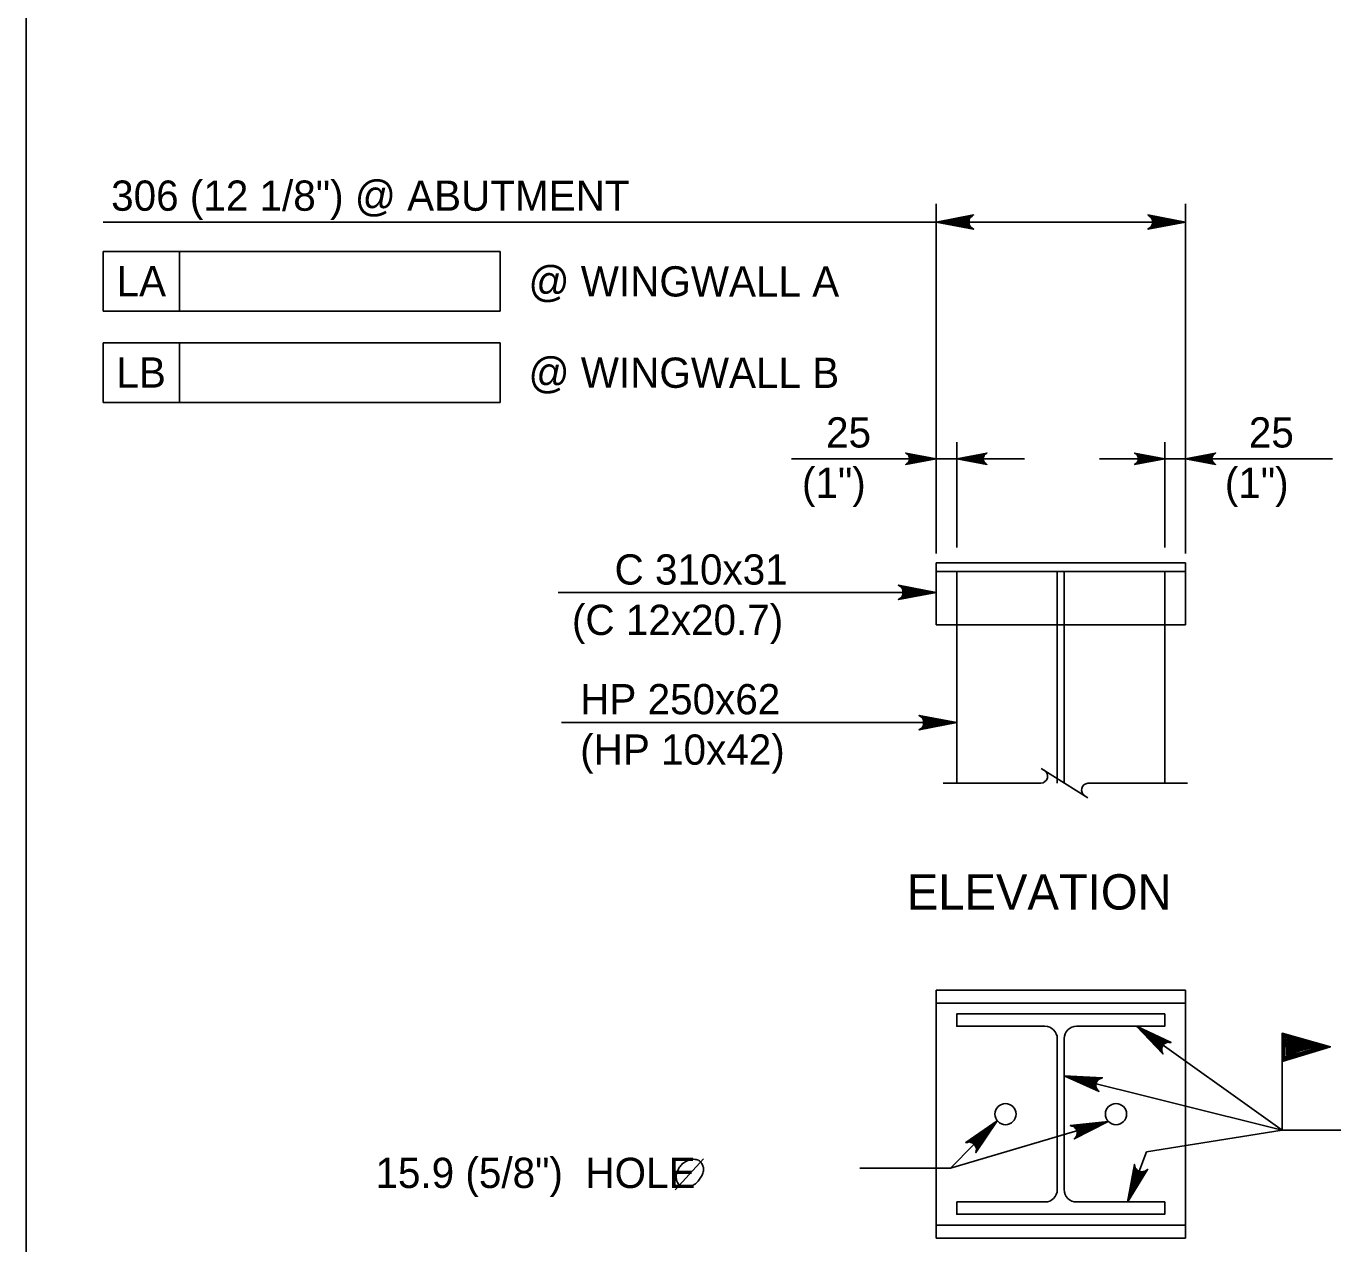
# Model space of a CAD drawing. Extents: x 635440 to 640306, y 296653 to 298484.
# Drawn here: x 639316.5 to 639446.1, y 296943.8 to 297064.6 of the extents above; entities that cross this region are included whole.
import ezdxf

# ---------------------------------------------------------------- set-up
doc = ezdxf.new("R2010")
doc.units = 0
for name, color, linetype in [('1', 7, 'Continuous'), ('2', 7, 'Continuous'), ('3', 7, 'Continuous'), ('4', 7, 'Continuous'), ('5', 7, 'Continuous')]:
    doc.layers.add(name, color=color, linetype=linetype)

# ---------------------------------------------------------------- blocks, each defined once
blk = doc.blocks.new('HPILE')
at = {"layer": '3'}
for p, q in [((-0.122, -2.665), (-0.122, 2.665)), ((0.122, 2.665), (0.122, -2.665)), ((-3.673, -3.102), (-0.56, -3.102))]:
    blk.add_line(p, q, dxfattribs=at)
for points in [[(-0.56, 3.102), (-3.673, 3.102), (-3.673, 3.537), (3.673, 3.537), (3.673, 3.102), (0.56, 3.102)], [(0.56, -3.102), (3.673, -3.102), (3.673, -3.536), (-3.673, -3.536), (-3.673, -3.102)]]:
    blk.add_lwpolyline(points, dxfattribs=at)
for centre, start, end in [((-0.56, 2.665), 0, 90), ((0.56, 2.665), 90, 180), ((-0.56, -2.665), 270, 0), ((0.56, -2.665), 180, 270)]:
    blk.add_arc(centre, 0.438, start, end, dxfattribs=at)
blk = doc.blocks.new('LT')
at = {"layer": '1'}
blk.add_lwpolyline([(0, 0), (-11.18, -2.1), (-10.75, -1.8), (-10.32, -1.5), (-10.1, -1.12), (-9.88, -0.75), (-9.81, -0.38), (-9.75, 0), (-9.81, 0.38), (-9.88, 0.75), (-10.1, 1.12), (-10.32, 1.5), (-10.75, 1.8), (-11.18, 2.1), (0, 0), (-10.75, 1.8), (-10.32, 1.5), (0, 0), (-10.1, 1.12), (-9.88, 0.75), (0, 0), (-9.81, 0.38), (-9.75, 0), (0, 0), (-9.81, -0.38), (-9.88, -0.75), (0, 0), (-10.1, -1.12), (-10.32, -1.5), (0, 0), (-10.75, -1.8)], dxfattribs=at)

msp = doc.modelspace()

# ---------------------------------------------------------------- linework, layer by layer
at = {"layer": '2'}
msp.add_line((639316.46, 296668.46), (639316.46, 297232.46), dxfattribs=at)
at = {"layer": '3'}
for p, q in [((639406.72, 297011.39), (639406.72, 297005.24)), ((639406.72, 297011.39), (639431.46, 297011.39)), ((639431.46, 297005.24), (639431.46, 297011.39)), ((639406.72, 297010.53), (639431.46, 297010.53)), ((639408.77, 297010.53), (639408.77, 297005.24)), ((639418.74, 297010.53), (639418.74, 296989.52)), ((639419.43, 297010.53), (639419.43, 296989.52)), ((639429.41, 297010.53), (639429.41, 297005.24)), ((639406.72, 297005.24), (639431.46, 297005.24)), ((639408.77, 297005.24), (639408.77, 296989.52)), ((639429.41, 296989.52), (639429.41, 297005.24)), ((639417.16, 296990.98), (639421.78, 296988.07)), ((639407.43, 296989.52), (639417.11, 296989.52)), ((639421.77, 296989.52), (639431.66, 296989.52)), ((639406.72, 296968.98), (639431.46, 296968.98)), ((639406.72, 296968.98), (639406.72, 296944.38)), ((639431.46, 296944.38), (639431.46, 296968.98)), ((639406.72, 296967.7), (639431.46, 296967.7)), ((639441.04, 296955.1), (639419.43, 296960.49)), ((639441.04, 296955.1), (639427.6, 296952.95)), ((639441.04, 296955.1), (639470.68, 296955.1)), ((639427.6, 296952.95), (639425.72, 296947.96)), ((639406.72, 296945.66), (639431.46, 296945.66)), ((639406.72, 296944.38), (639431.46, 296944.38))]:
    msp.add_line(p, q, dxfattribs=at)
for points in [[(639426.59, 296965.4), (639441.04, 296955.1)], [(639441.04, 296955.1), (639441.04, 296964.7), (639445.85, 296963.36), (639441.04, 296961.89), (639441.13, 296964.54), (639445.47, 296963.36), (639441.16, 296962.08), (639441.16, 296964.42), (639445.21, 296963.38), (639441.24, 296962.2), (639441.22, 296964.28), (639444.88, 296963.36), (639441.3, 296962.33), (639441.29, 296964.11), (639444.46, 296963.38), (639441.56, 296962.64), (639441.38, 296963.99), (639444.18, 296963.41), (639441.5, 296962.5), (639441.47, 296963.81), (639443.91, 296963.41), (639441.61, 296962.7), (639441.55, 296963.69), (639443.6, 296963.41), (639441.69, 296962.79), (639441.61, 296963.63), (639443.33, 296963.41), (639441.72, 296962.88), (639441.72, 296963.5), (639443.07, 296963.4), (639441.8, 296963.01), (639441.8, 296963.43), (639442.7, 296963.35), (639441.84, 296963.09), (639441.87, 296963.3), (639442.42, 296963.32), (639441.86, 296963.15), (639441.91, 296963.26), (639445.69, 296963.36), (639441.12, 296962), (639441.1, 296964.62)]]:
    msp.add_lwpolyline(points, dxfattribs=at)
for centre in [(639413.61, 296956.68), (639424.57, 296956.68)]:
    msp.add_circle(centre, 1.05, dxfattribs=at)
for centre, start, end in [((639417.11, 296990.21), 270, 60), ((639421.84, 296988.84), 95.3286, 237.8672)]:
    msp.add_arc(centre, 0.682, start, end, dxfattribs=at)
at = {"layer": '4'}
for p, q in [((639406.72, 297047.01), (639406.72, 297012.32)), ((639431.46, 297047.01), (639431.46, 297012.32)), ((639406.72, 297045.19), (639324.1, 297045.19)), ((639431.46, 297045.19), (639406.72, 297045.19)), ((639324.1, 297042.27), (639363.47, 297042.27)), ((639324.1, 297042.27), (639324.1, 297036.36)), ((639331.66, 297042.27), (639331.66, 297036.36)), ((639363.47, 297042.27), (639363.47, 297036.36)), ((639324.1, 297036.36), (639363.47, 297036.36)), ((639324.1, 297033.21), (639363.47, 297033.21)), ((639324.1, 297033.21), (639324.1, 297027.3)), ((639331.66, 297033.21), (639331.66, 297027.3)), ((639363.47, 297033.21), (639363.47, 297027.3)), ((639324.1, 297027.3), (639363.47, 297027.3)), ((639408.77, 297023.36), (639408.77, 297012.91)), ((639429.41, 297023.36), (639429.41, 297012.91)), ((639415.5, 297021.71), (639392.38, 297021.71)), ((639446.06, 297021.71), (639422.94, 297021.71))]:
    msp.add_line(p, q, dxfattribs=at)
for points in [[(639406.72, 297045.19), (639410.45, 297045.89), (639410.3, 297045.79), (639410.16, 297045.69), (639410.08, 297045.57), (639410.01, 297045.44), (639409.99, 297045.32), (639409.97, 297045.19), (639409.99, 297045.07), (639410.01, 297044.94), (639410.08, 297044.82), (639410.16, 297044.69), (639410.3, 297044.59), (639410.45, 297044.49), (639406.72, 297045.19), (639410.3, 297044.59), (639410.16, 297044.69), (639406.72, 297045.19), (639410.08, 297044.82), (639410.01, 297044.94), (639406.72, 297045.19), (639409.99, 297045.07), (639409.97, 297045.19), (639406.72, 297045.19), (639409.99, 297045.32), (639410.01, 297045.44), (639406.72, 297045.19), (639410.08, 297045.57), (639410.16, 297045.69), (639406.72, 297045.19), (639410.3, 297045.79)], [(639431.46, 297045.19), (639427.73, 297044.49), (639427.87, 297044.59), (639428.02, 297044.69), (639428.09, 297044.82), (639428.17, 297044.94), (639428.19, 297045.07), (639428.21, 297045.19), (639428.19, 297045.32), (639428.17, 297045.44), (639428.09, 297045.57), (639428.02, 297045.69), (639427.87, 297045.79), (639427.73, 297045.89), (639431.46, 297045.19), (639427.87, 297045.79), (639428.02, 297045.69), (639431.46, 297045.19), (639428.09, 297045.57), (639428.17, 297045.44), (639431.46, 297045.19), (639428.19, 297045.32), (639428.21, 297045.19), (639431.46, 297045.19), (639428.19, 297045.07), (639428.17, 297044.94), (639431.46, 297045.19), (639428.09, 297044.82), (639428.02, 297044.69), (639431.46, 297045.19), (639427.87, 297044.59)], [(639406.72, 297008.45), (639369.24, 297008.45)], [(639406.72, 297008.45), (639402.99, 297007.75), (639403.13, 297007.85), (639403.28, 297007.95), (639403.35, 297008.07), (639403.42, 297008.2), (639403.44, 297008.32), (639403.47, 297008.45), (639403.44, 297008.57), (639403.42, 297008.7), (639403.35, 297008.82), (639403.28, 297008.95), (639403.13, 297009.05), (639402.99, 297009.15), (639406.72, 297008.45), (639403.13, 297009.05), (639403.28, 297008.95), (639406.72, 297008.45), (639403.35, 297008.82), (639403.42, 297008.7), (639406.72, 297008.45), (639403.44, 297008.57), (639403.47, 297008.45), (639406.72, 297008.45), (639403.44, 297008.32), (639403.42, 297008.2), (639406.72, 297008.45), (639403.35, 297008.07), (639403.28, 297007.95), (639406.72, 297008.45), (639403.13, 297007.85)], [(639408.77, 296995.52), (639369.56, 296995.52)], [(639408.77, 296995.52), (639405.04, 296994.82), (639405.18, 296994.92), (639405.33, 296995.02), (639405.4, 296995.15), (639405.47, 296995.27), (639405.49, 296995.4), (639405.52, 296995.52), (639405.49, 296995.65), (639405.47, 296995.77), (639405.4, 296995.9), (639405.33, 296996.02), (639405.18, 296996.12), (639405.04, 296996.22), (639408.77, 296995.52), (639405.18, 296996.12), (639405.33, 296996.02), (639408.77, 296995.52), (639405.4, 296995.9), (639405.47, 296995.77), (639408.77, 296995.52), (639405.49, 296995.65), (639405.52, 296995.52), (639408.77, 296995.52), (639405.49, 296995.4), (639405.47, 296995.27), (639408.77, 296995.52), (639405.4, 296995.15), (639405.33, 296995.02), (639408.77, 296995.52), (639405.18, 296994.92)], [(639426.59, 296965.4), (639430.04, 296963.8), (639429.86, 296963.8), (639429.69, 296963.81), (639429.55, 296963.75), (639429.42, 296963.69), (639429.33, 296963.6), (639429.24, 296963.51), (639429.19, 296963.39), (639429.13, 296963.28), (639429.12, 296963.14), (639429.11, 296962.99), (639429.16, 296962.83), (639429.22, 296962.66), (639426.59, 296965.4), (639429.16, 296962.83), (639429.11, 296962.99), (639426.59, 296965.4), (639429.12, 296963.14), (639429.13, 296963.28), (639426.59, 296965.4), (639429.19, 296963.39), (639429.24, 296963.51), (639426.59, 296965.4), (639429.33, 296963.6), (639429.42, 296963.69), (639426.59, 296965.4), (639429.55, 296963.75), (639429.69, 296963.81), (639426.59, 296965.4), (639429.86, 296963.8)], [(639419.43, 296960.48), (639423.22, 296960.29), (639423.06, 296960.22), (639422.89, 296960.16), (639422.79, 296960.06), (639422.69, 296959.95), (639422.64, 296959.84), (639422.59, 296959.72), (639422.58, 296959.59), (639422.57, 296959.47), (639422.62, 296959.33), (639422.66, 296959.19), (639422.77, 296959.06), (639422.89, 296958.93), (639419.43, 296960.48), (639422.77, 296959.06), (639422.66, 296959.19), (639419.43, 296960.48), (639422.62, 296959.33), (639422.57, 296959.47), (639419.43, 296960.48), (639422.58, 296959.59), (639422.59, 296959.72), (639419.43, 296960.48), (639422.64, 296959.84), (639422.69, 296959.95), (639419.43, 296960.48), (639422.79, 296960.06), (639422.89, 296960.16), (639419.43, 296960.48), (639423.06, 296960.22)], [(639412.8, 296956.01), (639408.15, 296951.32), (639399.15, 296951.32)], [(639423.81, 296955.94), (639408.15, 296951.32)], [(639412.8, 296956.01), (639410.67, 296952.87), (639410.7, 296953.04), (639410.73, 296953.21), (639410.69, 296953.35), (639410.65, 296953.49), (639410.58, 296953.6), (639410.51, 296953.7), (639410.4, 296953.77), (639410.3, 296953.84), (639410.16, 296953.88), (639410.02, 296953.92), (639409.84, 296953.88), (639409.67, 296953.85), (639412.8, 296956.01), (639409.84, 296953.88), (639410.02, 296953.92), (639412.8, 296956.01), (639410.16, 296953.88), (639410.3, 296953.84), (639412.8, 296956.01), (639410.4, 296953.77), (639410.51, 296953.7), (639412.8, 296956.01), (639410.58, 296953.6), (639410.65, 296953.49), (639412.8, 296956.01), (639410.69, 296953.35), (639410.73, 296953.21), (639412.8, 296956.01), (639410.7, 296953.04)], [(639423.81, 296955.94), (639420.43, 296954.22), (639420.54, 296954.35), (639420.65, 296954.49), (639420.69, 296954.63), (639420.72, 296954.77), (639420.71, 296954.9), (639420.69, 296955.02), (639420.64, 296955.14), (639420.58, 296955.25), (639420.47, 296955.35), (639420.37, 296955.45), (639420.2, 296955.5), (639420.03, 296955.56), (639423.81, 296955.94), (639420.2, 296955.5), (639420.37, 296955.45), (639423.81, 296955.94), (639420.47, 296955.35), (639420.58, 296955.25), (639423.81, 296955.94), (639420.64, 296955.14), (639420.69, 296955.02), (639423.81, 296955.94), (639420.71, 296954.9), (639420.72, 296954.77), (639423.81, 296955.94), (639420.69, 296954.63), (639420.65, 296954.49), (639423.81, 296955.94), (639420.54, 296954.35)], [(639425.72, 296947.96), (639426.4, 296951.69), (639426.44, 296951.53), (639426.48, 296951.36), (639426.57, 296951.24), (639426.66, 296951.13), (639426.77, 296951.06), (639426.88, 296951), (639427, 296950.97), (639427.13, 296950.95), (639427.27, 296950.98), (639427.41, 296951), (639427.56, 296951.1), (639427.7, 296951.2), (639425.72, 296947.96), (639427.56, 296951.1), (639427.41, 296951), (639425.72, 296947.96), (639427.27, 296950.98), (639427.13, 296950.95), (639425.72, 296947.96), (639427, 296950.97), (639426.88, 296951), (639425.72, 296947.96), (639426.77, 296951.06), (639426.66, 296951.13), (639425.72, 296947.96), (639426.57, 296951.24), (639426.48, 296951.36), (639425.72, 296947.96), (639426.44, 296951.53)]]:
    msp.add_lwpolyline(points, dxfattribs=at)
at = {"layer": '5'}
msp.add_line((639380.85, 296949.18), (639383.65, 296952.24), dxfattribs=at)
msp.add_spline([(639383.36, 296951.94), (639383.14, 296952.11), (639382.92, 296952.17), (639382.65, 296952.2), (639382.49, 296952.2), (639382.22, 296952.13), (639381.98, 296952.02), (639381.8, 296951.92), (639381.47, 296951.66), (639381.22, 296951.32), (639381.06, 296951), (639380.97, 296950.71), (639380.94, 296950.45), (639380.97, 296950.21), (639381.08, 296949.88), (639381.2, 296949.71), (639381.44, 296949.53), (639381.8, 296949.45), (639382.22, 296949.46), (639382.74, 296949.7), (639383.12, 296950.02), (639383.4, 296950.42), (639383.59, 296950.83), (639383.65, 296951.3), (639383.57, 296951.59), (639383.37, 296951.94)], degree=3, dxfattribs=at)

# ---------------------------------------------------------------- block references
at = {"layer": '3', "xscale": 2.8100040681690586, "yscale": 2.8100040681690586}
msp.add_blockref('HPILE', (639419.09, 296956.68), dxfattribs=at)
at = {"layer": '4', "xscale": 0.2682316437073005, "yscale": 0.2682366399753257}
for p in [(639406.72, 297021.71), (639429.41, 297021.71)]:
    msp.add_blockref('LT', p, dxfattribs=at)
at = {"layer": '4', "xscale": 0.2682316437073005, "yscale": 0.2682366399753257, "rotation": 180}
for p in [(639408.77, 297021.71), (639431.46, 297021.71)]:
    msp.add_blockref('LT', p, dxfattribs=at)

# ---------------------------------------------------------------- texts
at = {"layer": '4'}
for s, height, p in [('306 (12 1/8") @ ABUTMENT', 3.0001, (639324.89, 297046.31)), ('LA', 3, (639325.43, 297037.82)), ('LB', 3, (639325.41, 297028.76)), ('25', 3, (639395.81, 297022.82)), ('25', 3, (639437.75, 297022.82)), ('(1")', 3, (639393.42, 297017.82)), ('(1")', 3, (639435.37, 297017.82)), ('C 310x31', 3, (639374.83, 297009.22)), ('(C 12x20.7)', 3.0001, (639370.6, 297004.22)), ('HP 250x62', 3, (639371.42, 296996.35)), ('(HP 10x42)', 3, (639371.42, 296991.35)), ('ELEVATION', 3.5, (639403.82, 296976.98)), ('15.9 (5/8")  HOLE', 3.0001, (639351.11, 296949.35))]:
    msp.add_text(s, height=height, dxfattribs=at).set_placement(p)
for s, p in [('@ WINGWALL A', (639366.29, 297037.82)), ('@ WINGWALL B', (639366.29, 297028.76))]:
    msp.add_text(s, height=3.0001, rotation=359.9382, dxfattribs=at).set_placement(p)

doc.saveas('drawing.dxf')
